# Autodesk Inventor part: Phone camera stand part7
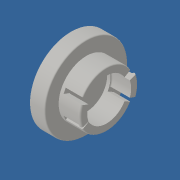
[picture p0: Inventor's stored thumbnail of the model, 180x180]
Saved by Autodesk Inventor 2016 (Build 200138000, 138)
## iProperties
Created: 2016-03
Part Number: Phone camera stand part7
Material: Generic
Document SubType Name: Modeling
Designer: Miha
Density: 1 g/cm^3
Appearance: Default
Author: Miha
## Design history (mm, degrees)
sketch "Sketch1"
  geometry: C1 r 10.7 at (0, 0); C2 r 8 at (0, 0); 1 further point
  constraints: 2 centre point, 2 coincident
  dimensions: "d0" = 21.4 diameter of C1; "d1" = 16 diameter of C2
extrude "Extrusion1" new body sketch "Sketch1" distance "d2" = 7.8; taper "d3" = 0 deg
sketch "Sketch2"
  geometry: C1 r 16 at (0, 0); 1 further point
  constraints: 1 centre point, 1 coincident
  dimensions: "d4" = 32 diameter of C1
extrude "Extrusion2" join sketch "Sketch2" distance "d5" = 6; taper "d6" = 0 deg
sketch "Sketch3"
  geometry: L1 (2.736, -7.518)-(3.66, -10.055); L2 (0, 0)-(11.127, 0); L3 (2.736, 7.518)-(3.66, 10.055); L4 (0, 0)-(14.787, 0); L5 (-2.736, 7.518)-(-3.66, 10.055); L6 (-2.736, -7.518)-(-3.66, -10.055); L7 (4, 6.928)-(5.35, 9.266); L8 (0, 0)-(16.872, 0); L9 (4, -6.928)-(5.35, -9.266); L10 (0, 0)-(16.305, 0); L11 (-4, -6.928)-(-5.35, -9.266); L12 (-4, 6.928)-(-5.35, 9.266); L13 (4.057, 6.895)-(5.35, 9.266); L14 (2.725, 7.522)-(3.678, 10.048); A1 r 8 centre (0, 0) between (2.725, 7.522) and (4.057, 6.895) reference; A2 r 8 centre (0, 0) between (4.057, 6.895) and (2.725, 7.522); A3 r 8 centre (0, 0) between (4.057, 6.895) and (2.725, 7.522); A4 r 10.7 centre (0, 0) between (5.35, 9.266) and (3.66, 10.055); A5 r 10.7 centre (0, 0) between (5.35, 9.266) and (3.66, 10.055); A6 r 10.7 centre (0, 0) between (-3.66, 10.055) and (-5.35, 9.266); A7 r 10.7 centre (0, 0) between (-3.66, 10.055) and (-5.35, 9.266); A8 r 8 centre (0, 0) between (-2.736, 7.518) and (-4, 6.928); A9 r 8 centre (0, 0) between (-2.736, 7.518) and (-4, 6.928); A10 r 10.7 centre (0, 0) between (-5.35, -9.266) and (-3.66, -10.055); A11 r 10.7 centre (0, 0) between (3.66, -10.055) and (5.35, -9.266); A12 r 10.7 centre (0, 0) between (-5.35, -9.266) and (-3.66, -10.055); A13 r 10.7 centre (0, 0) between (3.66, -10.055) and (5.35, -9.266); A14 r 8 centre (0, 0) between (-4, -6.928) and (-2.736, -7.518); A15 r 8 centre (0, 0) between (2.736, -7.518) and (4, -6.928); A16 r 8 centre (0, 0) between (-4, -6.928) and (-2.736, -7.518); A17 r 8 centre (0, 0) between (2.736, -7.518) and (4, -6.928); 7 further points
  constraints: 37 point on circle, 28 end point, 16 centre point, 4 horizontal, 3 coincident, 2 other
  dimensions: "d7" = 70 deg angle of L1 L2; "d8" = 70 deg angle of L4 L3; "d9" = 60 deg angle of L8 L7; "d10" = 60 deg angle of L9 L10
extrude "Extrusion3" cut sketch "Sketch3" distance "d11" = 6.5; taper "d12" = 0 deg
sketch "Sketch4"
  geometry: L1 (-4, 6.928)-(-5.35, 9.266) reference; L2 (-4, 6.928)-(-5.35, 9.266) reference; L3 (-4.25, 7.361)-(-4, 6.928); L4 (-3.66, 10.055)-(-2.736, 7.518) reference; L5 (-2.907, 7.987)-(-2.736, 7.518); L6 (2.736, 7.518)-(3.66, 10.055) reference; L7 (2.907, 7.987)-(2.736, 7.518); L8 (3.66, -10.055)-(2.736, -7.518) reference; L9 (2.907, -7.987)-(2.736, -7.518); L10 (2.736, -7.518)-(2.625, -7.824); L11 (-2.736, -7.518)-(-3.66, -10.055) reference; L12 (-2.736, -7.518)-(-2.907, -7.987); A1 r 10.7 centre (0, 0) between (-5.35, 9.266) and (-5.35, -9.266) reference; A2 r 10.7 centre (0, 0) between (3.66, 10.055) and (3.66, -10.055); A3 r 8 centre (0, 0) between (-4, 6.928) and (-4, -6.928) reference; A4 r 8 centre (0, 0) between (-4, 6.928) and (-4, -6.928) reference; A5 r 8 centre (0, 0) between (2.736, 7.518) and (-2.736, 7.518) reference; A6 r 8 centre (0, 0) between (-2.736, -7.518) and (2.736, -7.518); A7 r 8 centre (0, 0) between (2.736, 7.518) and (-2.736, 7.518); A8 r 8.5 centre (0, 0) between (-2.907, -7.987) and (2.907, -7.987); A9 r 8.5 centre (0, 0) between (2.907, 7.987) and (-2.907, 7.987); 1 further point
  constraints: 14 end point, 11 point on circle, 6 point on line, 5 centre point, 4 collinear, 3 coincident, 1 parallel
extrude "Extrusion4" cut sketch "Sketch4" distance "d14" = 6.5; taper "d15" = 0 deg
sketch "Sketch5"
  geometry: L1 (-3.66, 10.055)-(-2.907, 7.987) reference; L2 (-2.907, 7.987)-(-3.66, 10.055); L3 (2.907, 7.987)-(3.66, 10.055) reference; L4 (2.907, 7.987)-(3.66, 10.055); L5 (-3.66, 10.055)-(-3.814, 10.478); L6 (3.66, 10.055)-(3.814, 10.478); L7 (-2.907, -7.987)-(-3.66, -10.055) reference; L8 (-2.907, -7.987)-(-3.66, -10.055); L9 (-3.66, -10.055)-(-3.814, -10.478); L10 (3.66, -10.055)-(2.907, -7.987) reference; L11 (2.907, -7.987)-(3.66, -10.055); L12 (3.66, -10.055)-(3.814, -10.478); A1 r 8.5 centre (0, 0) between (2.907, 7.987) and (-2.907, 7.987) reference; A2 r 10.7 centre (0, 0) between (3.66, 10.055) and (-3.66, 10.055) reference; A3 r 8.5 centre (0, 0) between (-2.907, -7.987) and (2.907, -7.987); A4 r 8.5 centre (0, 0) between (2.907, 7.987) and (-2.907, 7.987); A5 r 11.15 centre (0, 0) between (-3.814, -10.478) and (3.814, -10.478); A6 r 11.15 centre (0, 0) between (3.814, 10.478) and (-3.814, 10.478); 1 further point
  constraints: 16 end point, 8 point on circle, 4 centre point, 4 collinear, 2 coincident, 2 point on line
extrude "Extrusion5" join sketch "Sketch5" distance "d17" = 1; taper "d18" = 0 deg
fillet "Fillet1" dims "d19" = 0.4
fillet "Fillet2" dims "d20" = 0.4
fillet "Fillet3" dims "d21" = 0.6
fillet "Fillet4" dims "d22" = 0.2
fillet "Fillet5" dims "d23" = 0.4
fillet "Fillet6" dims "d24" = 0.4
fillet "Fillet8" dims "d26" = 0.4
sketch "Sketch6"
  geometry: L1 (0, 15.6)-(0, -15.6); L2 (6, 7)-(6, -7); L3 (-6, 7)-(-6, -7); L4 (-11.05, 7)-(-11.05, -7); L5 (11.05, 7)-(11.05, -7); L6 (15.6, 0)-(11.05, 0); L7 (6, 0)-(-6, 0); L8 (-11.05, 0)-(-15.6, 0); L9 (11.05, 7)-(6, 7); L10 (-6, 7)-(-11.05, 7); L11 (11.05, -7)-(6, -7); L12 (-6, -7)-(-11.05, -7); 1 further point
  constraints: 24 end point, 16 parallel, 4 midpoint, 1 vertical
  dimensions: "d27" = 6 distance between parallel lines of L1 L2; "d28" = 6 distance between parallel lines of L1 L3; "d29" = 5.05 distance between parallel lines of L3 L4; "d30" = 5.05 distance between parallel lines of L2 L5; "d35" = 7 distance between parallel lines of L10 L7; "d36" = 7 distance between parallel lines of L9 L7; "d37" = 7 distance between parallel lines of L11 L7; "d38" = 7 distance between parallel lines of L12 L7
extrude "Extrusion6" cut sketch "Sketch6" distance "d39" = 5; taper "d40" = 0 deg
fillet "Fillet9" dims "d41" = 0.4
fillet "Fillet10" dims "d42" = 0.4
body "Solid1"
other parameters: "d13" = 17, "d16" = 22.3, "d31" = 7, "d32" = 7, "d33" = 7, "d34" = 7
